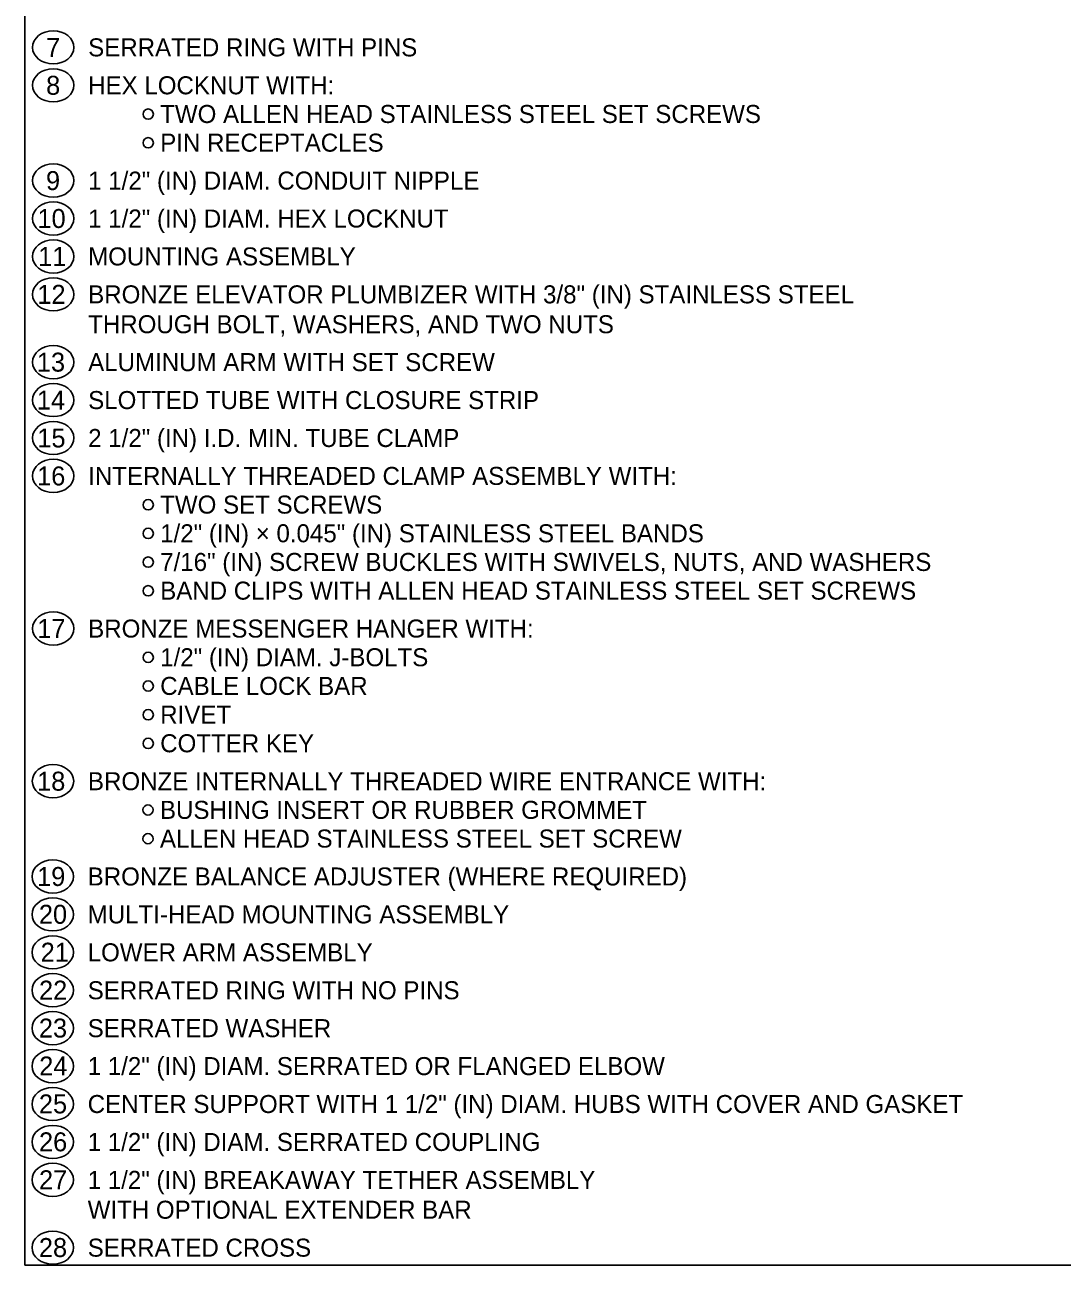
# Model space of a CAD drawing. Extents: x 99862 to 104211, y 98939 to 105076.
# Drawn here: x 99862 to 100738, y 100000 to 101046 of the extents above; entities that cross this region are included whole.
import ezdxf

# ---------------------------------------------------------------- set-up
doc = ezdxf.new("R2010")
doc.units = 0
for name, color, linetype in [('Level 1', 7, 'Continuous'), ('Level 16', 7, 'Continuous'), ('Level 20', 7, 'Continuous'), ('Level 60', 7, 'Continuous')]:
    doc.layers.add(name, color=color, linetype=linetype)

msp = doc.modelspace()

# ---------------------------------------------------------------- linework, layer by layer
at = {"layer": 'Level 1'}
msp.add_lwpolyline([(99862, 99999.5), (103151, 99999.5), (103151, 102075.5), (99862, 102075.5)], close=True, dxfattribs=at)
at = {"layer": 'Level 20'}
for centre, start, end in [((99966.2, 100970.8), 0, 180), ((99966.2, 100970.8), 180, 0), ((99966.2, 100946.6), 0, 180), ((99966.2, 100946.6), 180, 0), ((99966.2, 100641.2), 0, 180), ((99966.2, 100641.2), 180, 0), ((99966.2, 100617), 0, 180), ((99966.2, 100617), 180, 0), ((99966.2, 100592.8), 0, 180), ((99966.2, 100592.8), 180, 0), ((99966.2, 100568.6), 0, 180), ((99966.2, 100568.6), 180, 0), ((99966.2, 100512.4), 0, 180), ((99966.2, 100512.4), 180, 0), ((99966.2, 100488.2), 0, 180), ((99966.2, 100488.2), 180, 0), ((99966.2, 100464), 0, 180), ((99966.2, 100464), 180, 0), ((99966.2, 100439.8), 0, 180), ((99966.2, 100439.8), 180, 0), ((99966, 100383.6), 0, 180), ((99966, 100383.6), 180, 0), ((99966, 100359.4), 0, 180), ((99966, 100359.4), 180, 0)]:
    msp.add_arc(centre, 4.33, start, end, dxfattribs=at)
for centre in [(99886, 101027.1), (99886, 100995.1), (99886, 100914.7), (99886, 100882.7), (99886, 100850.7), (99886, 100818.7), (99886, 100761.5), (99886, 100729.5), (99886, 100697.5), (99886, 100665.5), (99886, 100536.7), (99885.8, 100407.9), (99885.6, 100327.5), (99885.6, 100295.5), (99885.6, 100263.5), (99885.6, 100231.5), (99885.6, 100199.5), (99885.6, 100167.5), (99885.6, 100135.5), (99885.6, 100103.5), (99885.6, 100071.5), (99885.6, 100014.3)]:
    msp.add_ellipse(centre, major_axis=(-17.5, 0), ratio=0.8, dxfattribs=at)
at = {"layer": 'Level 60'}
msp.add_line((99862, 99999.5), (99862, 99999.5), dxfattribs=at)

# ---------------------------------------------------------------- texts
at = {"layer": 'Level 16'}
for s, p in [('SERRATED RING WITH PINS', (99915.5, 101019.5)), ('HEX LOCKNUT WITH:', (99915.5, 100987.5)), ('TWO ALLEN HEAD STAINLESS STEEL SET SCREWS', (99976.3, 100963.3)), ('PIN RECEPTACLES', (99976.3, 100939.1)), ('1 1/2" (IN) DIAM. CONDUIT NIPPLE ', (99915.5, 100907.1)), ('1 1/2" (IN) DIAM. HEX LOCKNUT ', (99915.5, 100875.1)), ('MOUNTING ASSEMBLY', (99915.5, 100843.1)), ('BRONZE ELEVATOR PLUMBIZER WITH 3/8" (IN) STAINLESS STEEL', (99915.5, 100811.1)), ('THROUGH BOLT, WASHERS, AND TWO NUTS', (99915.5, 100785.9)), ('ALUMINUM ARM WITH SET SCREW', (99915.5, 100753.9)), ('SLOTTED TUBE WITH CLOSURE STRIP ', (99915.5, 100721.9)), ('2 1/2" (IN) I.D. MIN. TUBE CLAMP', (99915.5, 100689.9)), ('INTERNALLY THREADED CLAMP ASSEMBLY WITH:', (99915.5, 100657.9)), ('TWO SET SCREWS', (99976.3, 100633.7)), ('1/2" (IN) × 0.045" (IN) STAINLESS STEEL BANDS', (99976.3, 100609.5)), ('7/16" (IN) SCREW BUCKLES WITH SWIVELS, NUTS, AND WASHERS', (99976.3, 100585.3)), ('BAND CLIPS WITH ALLEN HEAD STAINLESS STEEL SET SCREWS', (99976.3, 100561.1)), ('BRONZE MESSENGER HANGER WITH:', (99915.5, 100529.1)), ('1/2" (IN) DIAM. J-BOLTS', (99976.3, 100504.9)), ('CABLE LOCK BAR', (99976.3, 100480.7)), ('RIVET', (99976.3, 100456.5)), ('COTTER KEY', (99976.3, 100432.3)), ('BRONZE INTERNALLY THREADED WIRE ENTRANCE WITH:', (99915.3, 100400.3)), ('BUSHING INSERT OR RUBBER GROMMET', (99976.1, 100376.1)), ('ALLEN HEAD STAINLESS STEEL SET SCREW', (99976.1, 100351.9)), ('BRONZE BALANCE ADJUSTER (WHERE REQUIRED)', (99915.1, 100319.9)), ('MULTI-HEAD MOUNTING ASSEMBLY', (99915.1, 100287.9)), ('LOWER ARM ASSEMBLY', (99915.1, 100255.9)), ('SERRATED RING WITH NO PINS', (99915.1, 100223.9)), ('SERRATED WASHER', (99915.1, 100191.9)), ('1 1/2" (IN) DIAM. SERRATED OR FLANGED ELBOW', (99915.1, 100159.9)), ('CENTER SUPPORT WITH 1 1/2" (IN) DIAM. HUBS WITH COVER AND GASKET', (99915.1, 100127.9)), ('1 1/2" (IN) DIAM. SERRATED COUPLING', (99915.1, 100095.9)), ('1 1/2" (IN) BREAKAWAY TETHER ASSEMBLY', (99915.1, 100063.9)), ('WITH OPTIONAL EXTENDER BAR', (99915.1, 100038.7)), ('SERRATED CROSS', (99915.1, 100006.7))]:
    msp.add_text(s, height=15.2, dxfattribs=at).set_placement(p)
at = {"layer": 'Level 20'}
for s, p in [('7', (99880, 101019.1)), ('8', (99880, 100987.1)), ('9', (99879.9, 100906.7)), ('10', (99872.7, 100874.7)), ('11', (99873.3, 100842.7)), ('12', (99872.6, 100810.7)), ('13', (99872.2, 100753.5)), ('14', (99872.2, 100721.5)), ('15', (99872.6, 100689.5)), ('16', (99872.4, 100657.5)), ('17', (99872.5, 100528.7)), ('18', (99872.4, 100399.9)), ('19', (99872.4, 100319.5)), ('20', (99873.9, 100287.6)), ('21', (99875.4, 100255.6)), ('22', (99874, 100223.6)), ('23', (99873.9, 100191.6)), ('24', (99874.2, 100159.6)), ('25', (99873.9, 100127.6)), ('26', (99874, 100095.6)), ('27', (99874, 100063.6)), ('28', (99873.9, 100006.4))]:
    msp.add_text(s, height=16, dxfattribs=at).set_placement(p)

doc.saveas('drawing.dxf')
